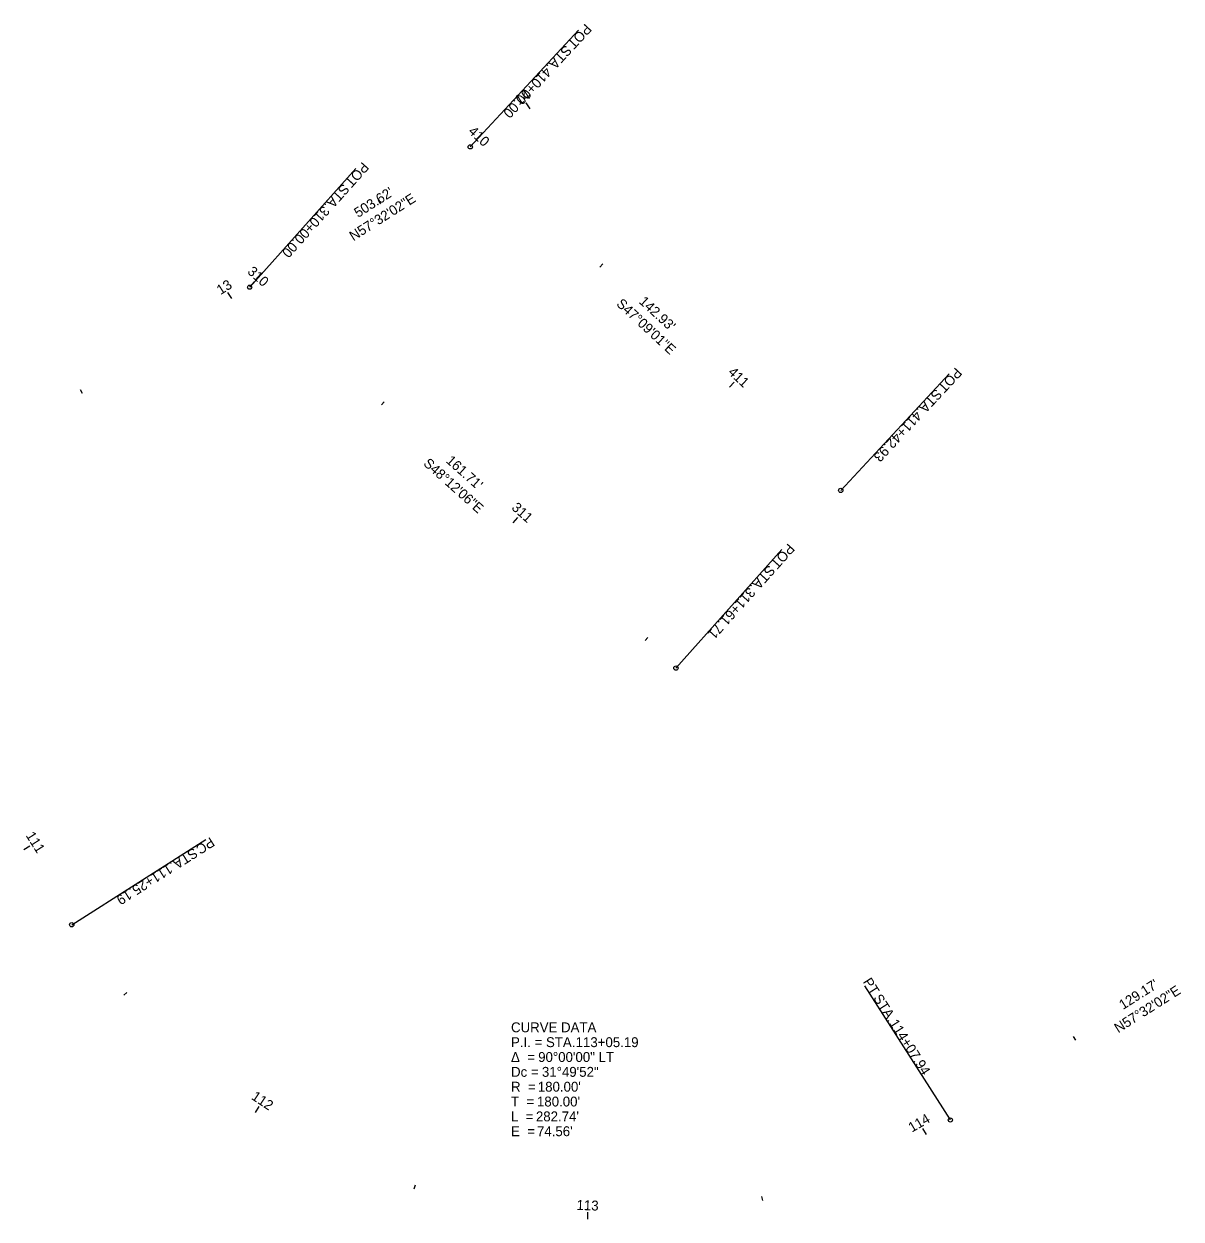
# Model space of a CAD drawing. Extents: x 143421 to 147121, y 511505 to 514560.
# Drawn here: x 145025.5 to 145352.8, y 512813.8 to 513152 of the extents above; entities that cross this region are included whole.
import ezdxf

# ---------------------------------------------------------------- set-up
doc = ezdxf.new("R2010")
doc.units = 0
for name, color, linetype in [('CM_Corridor_Top_Mesh', 7, 'Continuous'), ('DT_P_Tie', 7, 'Continuous'), ('DT_X_Triangles', 7, 'Continuous'), ('MD_P_Surface_Finished_Grade', 7, 'Continuous'), ('PF_X_Ground_Line', 7, 'Continuous')]:
    doc.layers.add(name, color=color, linetype=linetype)

msp = doc.modelspace()

# ---------------------------------------------------------------- linework, layer by layer
at = {"layer": 'DT_P_Tie'}
for p, q in [((145151.72, 513117.22), (145182.33, 513150.21)), ((145089.33, 513077.52), (145119.32, 513111.07)), ((145256.51, 513020.01), (145287.12, 513053)), ((145209.88, 512969.74), (145239.88, 513003.29)), ((145039.01, 512897.12), (145076.97, 512921.28)), ((145287.5, 512841.88), (145263.34, 512879.84))]:
    msp.add_line(p, q, dxfattribs=at)
for centre in [(145151.72, 513117.22), (145089.33, 513077.52), (145256.51, 513020.01), (145209.88, 512969.74), (145039.01, 512897.12), (145287.5, 512841.88)]:
    msp.add_circle(centre, 0.6, dxfattribs=at)
at = {"layer": 'DT_X_Triangles'}
for p, q in [((145168.64, 513127.98), (145167.57, 513129.67)), ((145151.72, 513117.22), (145153.08, 513118.69)), ((145126.46, 513101.14), (145125.81, 513102.16)), ((145188.38, 513083.22), (145189.2, 513084.1)), ((145089.33, 513077.52), (145090.66, 513079.01)), ((145084.27, 513074.3), (145083.2, 513075.99)), ((145042.09, 513047.46), (145041.44, 513048.48)), ((145225.04, 513049.21), (145226.4, 513050.68)), ((145126.61, 513044.2), (145127.41, 513045.09)), ((145163.88, 513010.87), (145165.21, 513012.36)), ((145201.16, 512977.55), (145201.96, 512978.44)), ((145025.48, 512918.38), (145027.17, 512919.45)), ((145053.72, 512877.17), (145054.63, 512877.95)), ((145322.99, 512864.46), (145322.34, 512865.47)), ((145090.94, 512844.03), (145092.05, 512845.69)), ((145280.71, 512837.76), (145279.71, 512839.5)), ((145135.83, 512822.37), (145136.19, 512823.51)), ((145234.49, 512819.11), (145234.2, 512820.27)), ((145184.93, 512813.84), (145185, 512815.84))]:
    msp.add_line(p, q, dxfattribs=at)

# ---------------------------------------------------------------- texts
at = {"layer": 'CM_Corridor_Top_Mesh'}
for s, rotation, p in [("503.62'", 32.4662, (145120, 513097.09)), ("142.93'", 317.1504, (145199.25, 513073.19)), ("161.71'", 318.2018, (145144.66, 513028.12)), ("129.17'", 32.4662, (145336.33, 512872.99))]:
    msp.add_text(s, height=2.8, rotation=rotation, dxfattribs=at).set_placement(p)
at = {"layer": 'DT_P_Tie'}
for s, rotation, p in [('POT', 227.1504, (145184.26, 513152.23)), (' STA. ', 227.1504, (145179.36, 513146.96)), ('410+00.00', 227.1504, (145172.94, 513140.03)), ('POT', 228.2018, (145121.22, 513113.13)), (' STA. ', 228.2018, (145116.42, 513107.76)), ('310+00.00', 228.2018, (145110.12, 513100.72)), ('POT', 227.1504, (145289, 513054.97)), (' STA. ', 227.1504, (145284.1, 513049.69)), ('411+42.93', 227.1504, (145277.68, 513042.76)), ('POT', 228.2018, (145241.64, 513005.2)), (' STA. ', 228.2018, (145236.84, 512999.84)), ('311+61.71', 228.2018, (145230.54, 512992.79)), ('PC', 212.4662, (145078.23, 512922.03)), (' STA. ', 212.4662, (145074.36, 512919.56)), ('111+25.19', 212.4662, (145066.39, 512914.49)), ('PT', 302.4662, (145262.66, 512880.99)), (' STA. ', 302.4662, (145265.03, 512877.26)), ('114+07.94', 302.4662, (145270.11, 512869.29))]:
    msp.add_text(s, height=2.8, rotation=rotation, dxfattribs=at).set_placement(p)
at = {"layer": 'DT_X_Triangles'}
for s, rotation, p in [('14', 32.4662, (145165.48, 513128.94)), ('410', 317.1504, (145150.97, 513121.33)), ('310', 318.2018, (145088.5, 513081.62)), ('13', 32.4662, (145081.11, 513075.26)), ('411', 317.1504, (145224.43, 513053.19)), ('311', 318.2018, (145163.2, 513014.84)), ('111', 302.4662, (145025.9, 512922.38)), ('112', 326.2777, (145089.6, 512847.93)), ('114', 29.9397, (145276.63, 512838.3)), ('113', 358.1087, (145181.74, 512816.45))]:
    msp.add_text(s, height=2.8, rotation=rotation, dxfattribs=at).set_placement(p)
at = {"layer": 'MD_P_Surface_Finished_Grade'}
for s, p in [('CURVE DATA', (145163.25, 512866.7)), ('P.I. = STA. ', (145163.25, 512862.5)), ('113+05.19', (145181.52, 512862.5)), ('Δ  = ', (145163.25, 512858.3)), ('90°00\'00" LT', (145170.93, 512858.3)), ('Dc = ', (145163.25, 512854.1)), ('31°49\'52"', (145171.99, 512854.1)), ('R  = ', (145163.25, 512849.9)), ("180.00'", (145170.83, 512849.9)), ('T  = ', (145163.25, 512845.7)), ("180.00'", (145170.59, 512845.7)), ('L  = ', (145163.25, 512841.5)), ("282.74'", (145170.29, 512841.5)), ('E  = ', (145163.25, 512837.3)), ("74.56'", (145170.59, 512837.3))]:
    msp.add_text(s, height=2.8, dxfattribs=at).set_placement(p)
at = {"layer": 'PF_X_Ground_Line'}
for s, rotation, p in [('N57°32\'02"E', 32.4662, (145118.65, 513090.49)), ('S47°09\'01"E', 317.1504, (145192.83, 513072.54)), ('S48°12\'06"E', 318.2018, (145138.25, 513027.35)), ('N57°32\'02"E', 32.4662, (145334.98, 512866.4))]:
    msp.add_text(s, height=2.8, rotation=rotation, dxfattribs=at).set_placement(p)

doc.saveas('drawing.dxf')
